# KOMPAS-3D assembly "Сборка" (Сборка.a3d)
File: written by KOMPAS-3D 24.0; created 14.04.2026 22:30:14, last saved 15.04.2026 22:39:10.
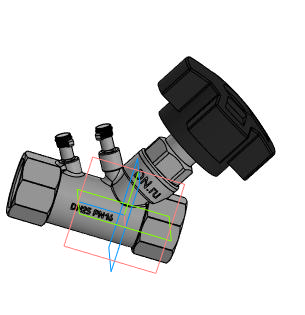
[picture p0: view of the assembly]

Document properties: Автор: tyuri; Полное имя файла: D:\Аутсорс\VB0000P-T Клапан балансировочный статический DN.ru\DN25\Сборка.a3d

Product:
- Component [detail]: Деталь1  | qty 1  | Автор: tyuri; additional columns: Типовые; source file: Деталь1 - Деталь1.m3d
- Body: Тело 1  | qty 1
    Масса: 0.566734
- Component [detail]: Ручка  | designation Деталь2  | qty 1  | Масса: 0.541971; Автор: tyuri; additional columns: Типовые; source file: Деталь2 - Деталь2.m3d
- Part/product: Сборка
    Масса: 1.108704

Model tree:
1. Эскиз:2  (labels: Грань.Твердое тело1)
2. Элемент вращения:1  (labels: Грань.Твердое тело1)
     Угол 1 = 360
3. Смещенная плоскость:1
     Расстояние = 40
4. Эскиз:3
5. Элемент выдавливания:1  (with: Грань.Элемент вращения:1)
     Расстояние 1 = -26.0649; Смещение 1 = 0.01
6. Эскиз:4
7. Элемент выдавливания:2  (with: Грань.Элемент вращения:1)  (labels: Ребро.Твердое тело1; Грань.Твердое тело1; Твердое тело1)
     Расстояние 1 = -25.0052; Смещение 1 = 0.001; Расстояние = 7

Referenced files in D:\Аутсорс\VB0000P-T Клапан балансировочный статический DN.ru\DN25\: Деталь1 - Деталь1.m3d, Деталь2 - Деталь2.m3d
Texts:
  DN25 PN16
  GOST 26.020 Pr3
  Деталь1 Деталь1
  Деталь2 Ручка
  Ось X.Начало координат
  Ось Z.Начало координат
  Плоскость ZY.Начало координат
